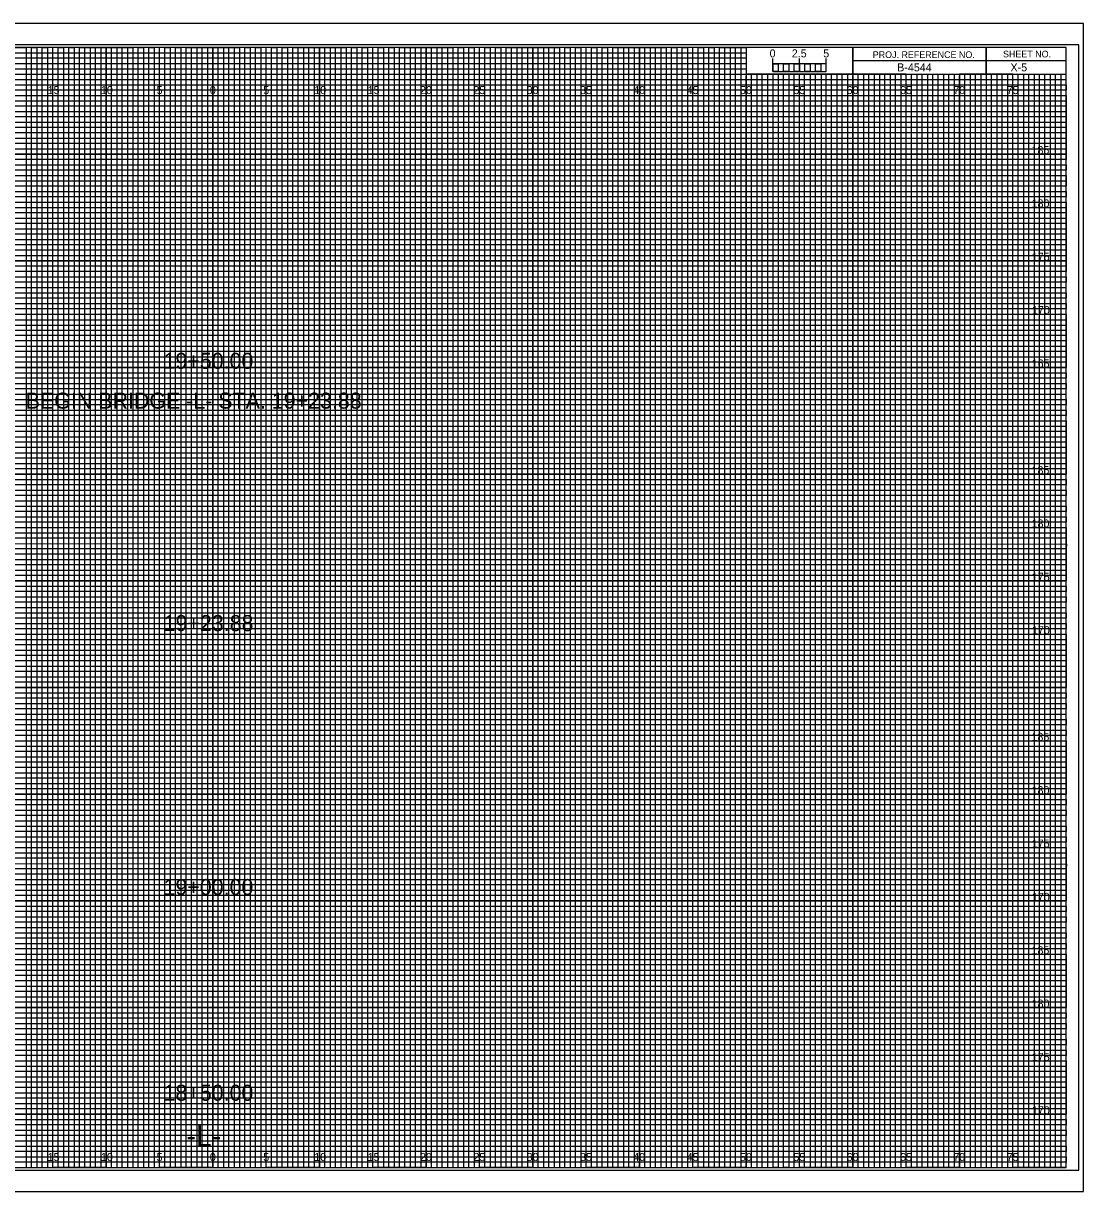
# Model space of a CAD drawing. Extents: x -7 to 162, y -2 to 767.
# Drawn here: x 62.2 to 161.7, y 437.8 to 547.2 of the extents above; entities that cross this region are included whole.
import ezdxf

# ---------------------------------------------------------------- set-up
doc = ezdxf.new("R2010")
doc.units = 0
for name, color, linetype in [('Exist CMT Pavement', 7, 'Continuous'), ('Exist Cross Section Cell', 7, 'Continuous'), ('Exist XS Ground Line', 7, 'Continuous'), ('Prop CMT Pvmt Course 1', 7, 'Continuous'), ('Prop CMT Pvmt Course 1 Wedge', 7, 'Continuous'), ('Prop CMT Pvmt Course 2', 7, 'Continuous'), ('Prop CMT Pvmt Course 2 Wedge', 7, 'Continuous'), ('Prop CMT Pvmt Course 3', 7, 'Continuous'), ('Prop CMT Pvmt Course 3 Wedge', 7, 'Continuous'), ('Prop CMT Pvmt Surface', 7, 'Continuous'), ('Prop CMT Pvmt Surface Shoulder', 7, 'Continuous'), ('Prop CMT Shld Paved Course 1', 7, 'Continuous'), ('Prop CMT Shld Paved Course 2', 7, 'Continuous'), ('Prop CMT Shld Paved Course 3', 7, 'Continuous'), ('Prop CMT Slope Grass', 7, 'Continuous'), ('Prop CMT Subgrade Earthwork', 7, 'Continuous'), ('Scratch_Level_0', 7, 'Continuous')]:
    doc.layers.add(name, color=color, linetype=linetype)

msp = doc.modelspace()

# ---------------------------------------------------------------- linework, layer by layer
at = {"layer": 'Prop CMT Pvmt Course 1'}
for p, q in [((0, 544.5), (130, 544.5)), ((130, 544.5), (130, 543.99)), ((130, 543.99), (0, 543.99)), ((0, 543.5), (130, 543.5)), ((130, 543.5), (130, 542.95)), ((130, 542.95), (0, 542.95)), ((0, 542), (160, 542))]:
    msp.add_line(p, q, dxfattribs=at)
for points in [[(0, 541.5), (135, 541.5), (160, 541.5), (160, 541), (0, 541)], [(0, 540.5), (160, 540.5), (160, 539.5), (0, 539.5)], [(0, 539), (160, 539), (160, 538.5), (0, 538.49)], [(0, 538), (160, 538), (160, 537), (0, 537)], [(0, 536.5), (160, 536.5), (160, 536), (0, 536)], [(0, 535.5), (160, 535.5), (160, 534.5), (0, 534.5)], [(0, 534), (160, 534), (160, 533.5), (0, 533.5)], [(0, 533), (160, 533), (160, 532), (0, 532)], [(0, 531.5), (160, 531.5), (160, 531), (0, 531)], [(0, 530.5), (160, 530.5), (160, 529.5), (0, 529.5)], [(0, 529), (160, 529), (160, 528.5), (0, 528.5)], [(0, 528), (160, 528), (160, 526.98), (160, 526.5), (160, 526), (0, 526)], [(0, 527), (160, 527), (160, 526.5), (0, 526.5)], [(0, 525.5), (160, 525.5), (160, 524.5), (0, 524.51)], [(0, 524.51), (160, 524.5), (160, 524), (0, 524)], [(0, 523.5), (160, 523.5), (160, 523), (0, 523)], [(0, 522), (160, 522), (160, 521.5), (0, 521.5)], [(0, 521), (160, 521), (160, 520.5), (0, 520.5)], [(-0.04, 519.45), (160, 519.45), (160, 518.94), (-0.04, 518.94)], [(0, 518.5), (160, 518.5), (160, 518), (0, 518)], [(0, 517), (160, 517), (160, 516.5), (0, 516.5)], [(0, 516), (160, 516), (160, 515.5), (0, 515.5)], [(0, 514.5), (160, 514.5), (160, 514), (0, 514)], [(0, 513.5), (160, 513.5), (160, 513), (0, 513)], [(0, 512), (160, 512), (160, 511.5), (0, 511.5)], [(0, 511), (160, 511), (160, 510.5), (0, 510.5)], [(0, 509.5), (160, 509.5), (160, 508.99), (0, 509)], [(0, 508.5), (160, 508.5), (160, 508), (0, 508)], [(0, 507), (160, 507), (160, 506.5), (0, 506.5)], [(0, 506), (160, 506), (160, 505.5), (0, 505.5)], [(0, 504.5), (160, 504.5), (160, 504), (0, 504)], [(0, 503.5), (160, 503.5), (160, 503), (0, 503)], [(0, 502), (160, 502), (160, 501.5), (0, 501.5)], [(0, 501), (160, 501), (160, 500.5), (0, 500.5)], [(0, 499.5), (160, 499.5), (160, 499), (0, 499)], [(0, 498.5), (160.03, 498.45), (160, 498), (0, 498)], [(0, 497), (160, 497), (160, 496.5), (0, 496.5)], [(0, 496), (160, 496), (160, 495.5), (0, 495.5)], [(0, 494.5), (160, 494.5), (160, 494), (0, 494)], [(0, 493.5), (160, 493.5), (160, 493), (0, 493)], [(0, 492), (160, 492), (160, 491.5), (0, 491.5)], [(0, 491), (160, 491), (160, 490.5), (0, 490.5)], [(0, 489.5), (160, 489.5), (160, 489), (0, 489)], [(0, 488.5), (160, 488.5), (160, 488), (0, 488)], [(0, 487), (160, 487), (160, 486.5), (0, 486.5)], [(0, 486), (160, 486), (160, 485.5), (0, 485.5)], [(0, 484.5), (160, 484.5), (160, 484), (0, 484)], [(0, 483.5), (160, 483.5), (160, 483), (0, 483)], [(0, 482), (160, 482), (160, 481.5), (0, 481.5)], [(0, 481), (160, 481), (160, 480.5), (0, 480.5)], [(0, 479.5), (160, 479.5), (160, 478.99), (0, 479)], [(0, 478.5), (160, 478.5), (160, 478), (0, 478)], [(0, 477), (160, 477), (160, 476.5), (0, 476.5)], [(0, 476), (160, 476), (160, 475.5), (0, 475.5)], [(0, 474.5), (160, 474.5), (160, 474), (0, 474)], [(0, 473.5), (160, 473.5), (160, 473), (0, 473)], [(0, 472), (160, 472), (160, 471.5), (0, 471.5)], [(0, 471), (160, 471), (160, 470.5), (0, 470.5)], [(0, 469.5), (160, 469.5), (160, 469), (0, 469)], [(0, 468.5), (160.03, 468.45), (160, 468), (0, 468)], [(0, 467), (160, 467), (160, 466.5), (0, 466.5)], [(0, 466), (160, 466), (160, 465.5), (0, 465.5)], [(0, 464.5), (160, 464.5), (160, 464), (0, 464)], [(0, 463.5), (160, 463.5), (160, 463), (0, 463)], [(0, 462), (160, 462), (160, 461.5), (0, 461.5)], [(0, 461), (160, 461), (160, 460.5), (0, 460.5)], [(0, 459.5), (160, 459.5), (160, 459), (0, 459)], [(0, 458.5), (160, 458.5), (160, 458), (0, 458)], [(0, 457), (160, 457), (160, 456.5), (0, 456.5)], [(0, 456), (160, 456), (160, 455.5), (0, 455.5)], [(0, 454.5), (160, 454.5), (160, 454), (0, 454)], [(0, 453.5), (160, 453.5), (160, 453), (0, 453)], [(0, 452), (160, 452), (160, 451.5), (0, 451.5)], [(0, 451), (160, 451), (160, 450.5), (0, 450.5)], [(0, 449.5), (160, 449.5), (160, 449), (0, 449)], [(0, 448.5), (160, 448.5), (160, 448), (0, 448)], [(0, 447), (160, 447), (160, 446.5), (0, 446.5)], [(0, 446), (160, 446), (160, 445.5), (0, 445.5)], [(0, 444.5), (160, 444.5), (160, 444), (0, 444)], [(0, 443.5), (160, 443.5), (160, 443), (0, 443)], [(0, 442), (160, 442), (160, 441.5), (0, 441.5)], [(0, 441), (160, 441), (160, 440.5), (0, 440.5)]]:
    msp.add_lwpolyline(points, dxfattribs=at)
at = {"layer": 'Prop CMT Pvmt Course 2'}
for p, q in [((65, 440), (65, 545)), ((70, 440), (70, 545)), ((75, 440), (75, 545)), ((80, 440), (80, 545)), ((85, 440), (85, 545)), ((90, 440), (90, 545)), ((95, 440), (95, 545)), ((100, 440), (100, 545)), ((105, 440), (105, 545)), ((110, 440), (110, 545)), ((115, 440), (115, 545)), ((120, 440), (120, 545)), ((125, 440), (125, 545)), ((130, 440), (130, 542.34)), ((135, 440), (135, 542.34)), ((140, 440), (140, 542.34)), ((145, 440), (145, 542.34)), ((150, 440), (150, 542.34)), ((155, 440), (155, 542.34)), ((0, 540), (160, 540)), ((0, 535), (160, 535)), ((0, 530), (160, 530)), ((0, 525), (160, 525)), ((0, 520), (160, 520)), ((0, 515), (160, 515)), ((0, 510), (160, 510)), ((0, 505), (160, 505)), ((0, 500), (160, 500)), ((0, 495), (160, 495)), ((0, 490), (160, 490)), ((0, 485), (160, 485)), ((0, 480), (160, 480)), ((0, 475), (160, 475)), ((0, 470), (160, 470)), ((0, 465), (160, 465)), ((0, 460), (160, 460)), ((0, 455), (160, 455)), ((0, 450), (160, 450)), ((0, 445), (160, 445))]:
    msp.add_line(p, q, dxfattribs=at)
at = {"layer": 'Prop CMT Pvmt Course 3'}
for p, q in [((161.65, 547.25), (-6.7, 547.25)), ((-6.7, 437.75), (161.65, 437.75))]:
    msp.add_line(p, q, dxfattribs=at)
at = {"layer": 'Prop CMT Pvmt Surface Shoulder'}
for points in [[(57.5, 545), (62.5, 545), (62.5, 440), (67.5, 440), (67.5, 545), (72.5, 545), (72.5, 440), (77.5, 440), (77.5, 545), (82.5, 545), (82.5, 440), (87.5, 440), (87.5, 545), (92.5, 545), (92.5, 440), (97.5, 440), (97.5, 545), (102.5, 545), (102.5, 440), (107.5, 440), (107.5, 545), (112.5, 545), (112.5, 440), (117.5, 440), (117.5, 545), (122.5, 545), (122.5, 440), (127.5, 440), (127.5, 545), (129.97, 545), (130, 545), (130, 542.5), (132.5, 542.5), (132.5, 440), (137.5, 440), (137.5, 542.5), (142.5, 542.5), (142.5, 440), (147.5, 440), (147.5, 542.5), (152.5, 542.5), (152.5, 440), (157.5, 440), (157.5, 542.5)], [(0, 542.5), (137.5, 542.5)], [(0, 532.5), (160, 532.5), (160, 537.5), (0, 537.5)], [(0, 522.5), (160, 522.5), (160, 527.5), (0, 527.5)], [(0, 512.5), (160, 512.5), (160, 517.5), (0, 517.5)], [(0, 502.5), (160, 502.5), (160, 507.5), (0, 507.5)], [(0, 492.5), (160, 492.5), (160, 497.5), (0, 497.5)], [(0, 482.5), (160, 482.5), (160, 487.5), (0, 487.5)], [(0, 472.5), (160, 472.5), (160, 477.5), (0, 477.5)], [(0, 462.5), (160, 462.5), (160, 467.5), (0, 467.5)], [(0, 452.5), (160, 452.5), (160, 457.5), (0, 457.5)], [(0, 442.5), (160, 442.5), (160, 447.5), (0, 447.5)]]:
    msp.add_lwpolyline(points, dxfattribs=at)
at = {"layer": 'Prop CMT Shld Paved Course 1'}
for p, q in [((132.5, 542.75), (132.5, 543.95)), ((132.5, 543.45), (132.5, 543.95)), ((135, 542.75), (135, 543.95)), ((137.5, 542.75), (137.5, 543.95)), ((137.5, 543.45), (137.5, 543.95))]:
    msp.add_line(p, q, dxfattribs=at)
for points in [[(137.5, 543.45), (132.5, 543.45), (132.5, 542.75), (137.5, 542.75)], [(132.5, 543.45), (133, 543.45), (133, 542.75), (132.5, 542.75)], [(133.5, 543.45), (134, 543.45), (134, 542.75), (133.5, 542.75)], [(134.5, 543.45), (135, 543.45), (135, 542.75), (134.5, 542.75)], [(135.5, 543.45), (136, 543.45), (136, 542.75), (135.5, 542.75)], [(136.5, 543.45), (137, 543.45), (137, 542.75), (136.5, 542.75)]]:
    msp.add_lwpolyline(points, close=True, dxfattribs=at)
at = {"layer": 'Prop CMT Shld Paved Course 2'}
msp.add_lwpolyline([(-6.7, 437.75), (161.65, 437.75), (161.65, 547.25), (-6.7, 547.25)], close=True, dxfattribs=at)
at = {"layer": 'Prop CMT Shld Paved Course 3'}
msp.add_lwpolyline([(-5.4, 439.75), (161.2, 439.75), (161.2, 545.25), (-5.4, 545.25)], close=True, dxfattribs=at)
at = {"layer": 'Prop CMT Slope Grass'}
for p, q in [((133.5, 542.5), (133, 542.5)), ((133, 542.5), (133, 440)), ((133.5, 440), (133.5, 542.5)), ((134.5, 542.5), (134, 542.5)), ((134, 542.5), (134, 440)), ((134.5, 440), (134.5, 542.5)), ((133, 440), (132.5, 440)), ((134, 440), (133.5, 440))]:
    msp.add_line(p, q, dxfattribs=at)
for points in [[(62.5, 440), (63, 440), (63, 545), (63.5, 545), (63.5, 440)], [(63.5, 440), (64, 440), (64, 545), (64.5, 545), (64.5, 440)], [(65, 440), (65.5, 440), (65.5, 545), (66, 545), (66, 440)], [(66, 440), (66.5, 440), (66.5, 545), (67, 545), (67, 440)], [(67.5, 440), (68, 440), (68, 545), (68.5, 545), (68.5, 440)], [(68.5, 440), (69, 440), (69, 545), (69.5, 545), (69.5, 440)], [(70, 440), (70.5, 440), (70.5, 545), (71, 545), (71, 440)], [(71, 440), (71.5, 440), (71.5, 545), (72, 545), (72, 440)], [(72.5, 440), (73, 440), (73, 545), (73.5, 545), (73.5, 440)], [(73.5, 440), (74, 440), (74, 545), (74.5, 545), (74.5, 440)], [(75, 440), (75.5, 440), (75.5, 545), (76, 545), (76, 440)], [(76, 440), (76.5, 440), (76.5, 545), (77, 545), (77, 440)], [(77.5, 440), (78, 440), (78, 545), (78.5, 545), (78.5, 440)], [(78.5, 440), (79, 440), (79, 545), (79.5, 545), (79.5, 440)], [(80, 440), (80.5, 440), (80.5, 545), (81, 545), (81, 440)], [(81, 440), (81.5, 440), (81.5, 545), (82, 545), (82, 440)], [(82.5, 440), (83, 440), (83, 545), (83.5, 545), (83.5, 440)], [(83.5, 440), (84, 440), (84, 545), (84.5, 545), (84.5, 440)], [(85, 440), (85.5, 440), (85.5, 545), (86, 545), (86, 440)], [(86, 440), (86.5, 440), (86.5, 545), (87, 545), (87, 440)], [(87.5, 440), (88, 440), (88, 545), (88.5, 545), (88.5, 440)], [(88.5, 440), (89, 440), (89, 545), (89.5, 545), (89.5, 440)], [(90, 440), (90.5, 440), (90.5, 545), (91, 545), (91, 440)], [(91, 440), (91.5, 440), (91.5, 545), (92, 545), (92, 440)], [(92.5, 440), (93, 440), (93, 545), (93.5, 545), (93.5, 440)], [(93.5, 440), (94, 440), (94, 545), (94.5, 545), (94.5, 440)], [(95, 440), (95.5, 440), (95.5, 545), (96, 545), (96, 440)], [(96, 440), (96.5, 440), (96.5, 545), (97, 545), (97, 440)], [(97.5, 440), (98, 440), (98, 545), (98.5, 545), (98.5, 440)], [(98.5, 440), (99, 440), (99, 545), (99.5, 545), (99.5, 440)], [(100, 440), (100.5, 440), (100.5, 545), (101, 545), (101, 440)], [(101, 440), (101.5, 440), (101.5, 545), (102, 545), (102, 440)], [(102.5, 440), (103, 440), (103, 545), (103.5, 545), (103.5, 440)], [(103.5, 440), (104, 440), (104, 545), (104.5, 545), (104.5, 440)], [(105, 440), (105.5, 440), (105.5, 545), (106, 545), (106, 440)], [(106, 440), (106.5, 440), (106.5, 545), (107, 545), (107, 440)], [(107.5, 440), (108, 440), (108, 545), (108.5, 545), (108.5, 440)], [(108.5, 440), (109, 440), (109, 545), (109.5, 545), (109.5, 440)], [(110, 440), (110.5, 440), (110.5, 545), (111, 545), (111, 440)], [(111, 440), (111.5, 440), (111.5, 545), (112, 545), (112, 440)], [(112.5, 440), (113, 440), (113, 545), (113.5, 545), (113.5, 440)], [(113.5, 440), (114, 440), (114, 545), (114.5, 545), (114.5, 440)], [(115, 440), (115.5, 440), (115.5, 545), (116, 545), (116, 440)], [(116, 440), (116.5, 440), (116.5, 545), (117, 545), (117, 440)], [(117.5, 440), (118, 440), (118, 545), (118.5, 545), (118.5, 440)], [(118.5, 440), (119, 440), (119, 545), (119.5, 545), (119.5, 440)], [(120, 440), (120.5, 440), (120.5, 545), (121, 545), (121, 440)], [(121, 440), (121.5, 440), (121.5, 545), (122, 545), (122, 440)], [(122.5, 440), (123, 440), (123, 545), (123.5, 545), (123.5, 440)], [(123.5, 440), (124, 440), (124, 545), (124.5, 545), (124.5, 440)], [(125, 440), (125.5, 440), (125.5, 545), (126, 545), (126, 440)], [(126, 440), (126.5, 440), (126.5, 545), (127, 545), (127, 440)], [(127.5, 440), (128, 440), (128, 545), (128.5, 545), (128.5, 440)], [(128.5, 440), (129, 440), (129, 545), (129.5, 545), (129.5, 440)], [(130, 440), (130.5, 440), (130.5, 542.5), (131.01, 542.5), (131.01, 440)], [(131, 440), (131.5, 440), (131.5, 542.5), (132, 542.5), (132, 440)], [(135, 440), (135.49, 440), (135.49, 542.5), (136, 542.5), (136, 440)], [(136, 440), (136.5, 440), (136.5, 542.5), (137.03, 542.5), (137.03, 440)], [(137.5, 440), (138, 440), (138, 542.5), (138.5, 542.5), (138.5, 440)], [(138.5, 440), (139, 440), (139, 542.5), (139.5, 542.5), (139.5, 440)], [(140, 440), (140.5, 440), (140.5, 542.5), (141, 542.5), (141, 440)], [(141, 440), (141.5, 440), (141.5, 542.5), (142, 542.5), (142, 440)], [(142.5, 440), (143, 440), (143, 542.5), (143.5, 542.5), (143.5, 440)], [(143.5, 440), (144, 440), (144, 542.5), (144.5, 542.5), (144.5, 440)], [(145, 440), (145.5, 440), (145.5, 542.5), (146, 542.5), (146, 440)], [(146, 440), (146.5, 440), (146.5, 542.5), (147, 542.5), (147, 440)], [(147.5, 440), (148, 440), (148, 542.5), (148.5, 542.5), (148.5, 440)], [(148.5, 440), (149, 440), (149, 542.5), (149.5, 542.5), (149.5, 440)], [(150, 440), (150.5, 440), (150.5, 542.5), (151, 542.5), (151, 440)], [(151, 440), (151.5, 440), (151.5, 542.5), (152, 542.5), (152, 440)], [(152.5, 440), (153, 440), (153, 542.5), (153.5, 542.5), (153.5, 440)], [(153.5, 440), (154, 440), (154, 542.5), (154.5, 542.5), (154.5, 440)], [(155, 440), (155.5, 440), (155.5, 542.5), (156, 542.5), (156, 440)], [(156, 440), (156.5, 440), (156.5, 542.5), (157, 542.5), (157, 440)], [(157.5, 440), (158, 440), (158, 542.5), (158.5, 542.5), (158.5, 440)], [(158.5, 440), (159, 440), (159, 542.5), (159.5, 542.5), (159.5, 440)]]:
    msp.add_lwpolyline(points, dxfattribs=at)
at = {"layer": 'Prop CMT Subgrade Earthwork'}
for p, q in [((152.5, 545), (152.5, 542.5)), ((152.5, 542.5), (152.5, 545)), ((160, 543.75), (140, 543.75)), ((140, 543.75), (140, 542.5)), ((140, 542.5), (160, 542.5))]:
    msp.add_line(p, q, dxfattribs=at)
for points in [[(160, 545), (0, 545), (0, 440), (160, 440)], [(140, 545), (130, 545), (130, 542.51), (140, 542.51)], [(160, 545), (140, 545), (140, 542.5), (160, 542.5)]]:
    msp.add_lwpolyline(points, close=True, dxfattribs=at)
at = {"layer": 'Scratch_Level_0'}
for p, q in [((65, 545), (60, 545)), ((65, 440), (65, 545)), ((75, 545), (70, 545)), ((70, 545), (70, 440)), ((75, 440), (75, 545)), ((85, 545), (80, 545)), ((80, 545), (80, 440)), ((85, 440), (85, 545)), ((95, 545), (90, 545)), ((90, 545), (90, 440)), ((95, 440), (95, 545)), ((105, 545), (100, 545)), ((100, 545), (100, 440)), ((105, 440), (105, 545)), ((115, 545), (110, 545)), ((110, 545), (110, 440)), ((115, 440), (115, 545)), ((125, 545), (120, 545)), ((120, 545), (120, 440)), ((125, 440), (125, 545)), ((130, 545), (130, 440)), ((135, 440), (135, 542.5)), ((145, 542.5), (140, 542.5)), ((140, 542.5), (140, 440)), ((145, 440), (145, 542.5)), ((155, 542.5), (150, 542.5)), ((150, 542.5), (150, 440)), ((155, 440), (155, 542.5)), ((70, 440), (65, 440)), ((80, 440), (75, 440)), ((90, 440), (85, 440)), ((100, 440), (95, 440)), ((110, 440), (105, 440)), ((120, 440), (115, 440)), ((130, 440), (125, 440)), ((140, 440), (135, 440)), ((150, 440), (145, 440)), ((160, 440), (155, 440)), ((160, 440), (160, 440))]:
    msp.add_line(p, q, dxfattribs=at)
for points in [[(0, 540), (160, 540), (160, 535), (0, 535)], [(0, 530), (160, 530), (160, 525), (0, 525)], [(0, 520), (160, 520), (160, 515), (0, 515)], [(0, 510), (160, 510), (160, 505), (0, 505)], [(0, 500), (160, 500), (160, 495), (0, 495)], [(0, 490), (160, 490), (160, 485), (0, 485)], [(0, 480), (160, 480), (160, 475), (0, 475)], [(0, 470), (160, 470), (160, 465), (0, 465)], [(0, 460), (160, 460), (160, 455), (0, 455)], [(0, 450), (160, 450), (160, 445), (0, 445)]]:
    msp.add_lwpolyline(points, dxfattribs=at)

# ---------------------------------------------------------------- texts
at = {"layer": 'Exist CMT Pavement'}
msp.add_text('B-4544', height=0.75, dxfattribs=at).set_placement((144.17, 542.75))
at = {"layer": 'Exist Cross Section Cell'}
for s, p in [('15', (64.53, 540.62)), ('10', (69.52, 540.62)), ('5', (74.74, 540.62)), ('0', (79.73, 540.62)), ('0', (79.73, 540.62)), ('5', (84.74, 540.62)), ('10', (89.52, 540.62)), ('15', (94.53, 540.62)), ('20', (99.43, 540.62)), ('25', (104.44, 540.62)), ('30', (109.43, 540.62)), ('35', (114.44, 540.62)), ('40', (119.43, 540.62)), ('45', (124.44, 540.62)), ('50', (129.43, 540.62)), ('55', (134.44, 540.62)), ('60', (139.43, 540.62)), ('65', (144.44, 540.62)), ('70', (149.43, 540.62)), ('75', (154.44, 540.62)), ('15', (64.53, 440.62)), ('10', (69.52, 440.62)), ('5', (74.74, 440.62)), ('0', (79.73, 440.62)), ('0', (79.73, 440.62)), ('5', (84.74, 440.62)), ('10', (89.52, 440.62)), ('15', (94.53, 440.62)), ('20', (99.43, 440.62)), ('25', (104.44, 440.62)), ('30', (109.43, 440.62)), ('35', (114.44, 440.62)), ('40', (119.43, 440.62)), ('45', (124.44, 440.62)), ('50', (129.43, 440.62)), ('55', (134.44, 440.62)), ('60', (139.43, 440.62)), ('65', (144.44, 440.62)), ('70', (149.43, 440.62)), ('75', (154.44, 440.62))]:
    msp.add_text(s, height=0.75, dxfattribs=at).set_placement(p)
at = {"layer": 'Exist XS Ground Line'}
for s, p in [('2.5', (134.29, 544.06)), ('5', (137.24, 544.06))]:
    msp.add_text(s, height=0.75, dxfattribs=at).set_placement(p)
at = {"layer": 'Prop CMT Pvmt Course 1 Wedge'}
for s, p in [('185', (156.76, 535)), ('180', (156.77, 530)), ('175', (156.79, 525)), ('170', (156.8, 520)), ('165', (156.78, 515)), ('185', (156.76, 505)), ('180', (156.77, 500)), ('175', (156.79, 495)), ('170', (156.8, 490)), ('185', (156.76, 480)), ('180', (156.77, 475)), ('175', (156.79, 470)), ('170', (156.8, 465)), ('185', (156.76, 460)), ('180', (156.77, 455)), ('175', (156.79, 450)), ('170', (156.8, 445))]:
    msp.add_text(s, height=0.75, dxfattribs=at).set_placement(p)
at = {"layer": 'Prop CMT Pvmt Course 2 Wedge'}
for s, p in [('19+50.00', (75.39, 514.87)), ('BEGIN BRIDGE -L- STA. 19+23.88', (62.47, 511.14)), ('19+23.88', (75.4, 490.29)), ('19+00.00', (75.39, 465.55)), ('18+50.00', (75.39, 446.27))]:
    msp.add_text(s, height=1.5, dxfattribs=at).set_placement(p)
at = {"layer": 'Prop CMT Pvmt Course 3 Wedge'}
msp.add_text('X-5', height=0.75, dxfattribs=at).set_placement((154.79, 542.75))
at = {"layer": 'Prop CMT Pvmt Surface'}
msp.add_text('-L-', height=2, dxfattribs=at).set_placement((77.53, 442))
at = {"layer": 'Prop CMT Shld Paved Course 1'}
msp.add_text('0', height=0.75, dxfattribs=at).set_placement((132.21, 544.06))
at = {"layer": 'Prop CMT Subgrade Earthwork'}
for s, p in [('PROJ. REFERENCE NO.', (141.88, 544)), ('SHEET NO.', (154.09, 544.06))]:
    msp.add_text(s, height=0.625, dxfattribs=at).set_placement(p)

doc.saveas('drawing.dxf')
